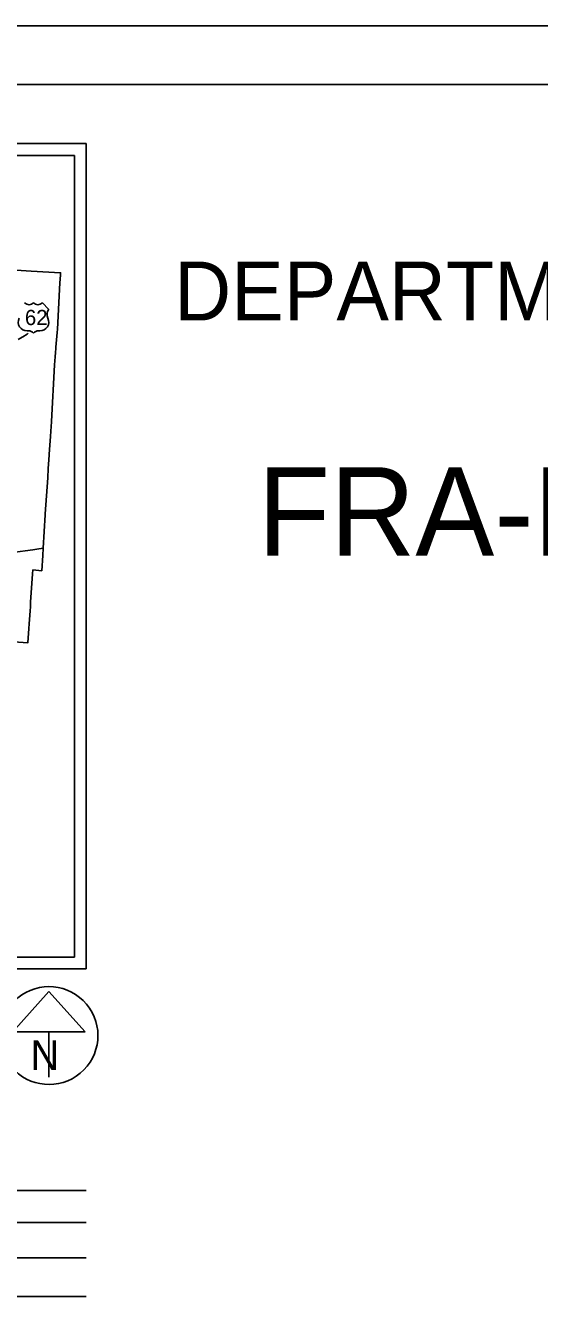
# Model space of a CAD drawing. Extents: x 0 to 34, y 0 to 22.
# Drawn here: x 8.49 to 12.84, y 11.1 to 22 of the extents above; entities that cross this region are included whole.
import ezdxf

# ---------------------------------------------------------------- set-up
doc = ezdxf.new("R2010")
doc.units = 0
for name, color, linetype in [('GM_X_County', 7, 'Continuous'), ('GM_X_State_Route', 7, 'Continuous'), ('GM_X_US_Route', 7, 'Continuous'), ('GM_X_US_Shield', 7, 'Continuous'), ('SH_Border', 7, 'Continuous'), ('SH_Cut_Line', 7, 'Continuous'), ('SH_Data', 7, 'Continuous'), ('SH_Text', 7, 'Continuous')]:
    doc.layers.add(name, color=color, linetype=linetype)

msp = doc.modelspace()

# ---------------------------------------------------------------- linework, layer by layer
at = {"layer": 'GM_X_County'}
msp.add_lwpolyline([(8.407, 19.926), (8.534, 19.918), (8.783, 19.905), (8.782, 19.883), (8.778, 19.818), (8.757, 19.427), (8.756, 19.425), (8.755, 19.398), (8.744, 19.273), (8.744, 19.263), (8.741, 19.229), (8.738, 19.191), (8.733, 19.123), (8.705, 18.642), (8.705, 18.641), (8.7, 18.562), (8.697, 18.517), (8.69, 18.405), (8.684, 18.317), (8.679, 18.246), (8.674, 18.165), (8.669, 18.09), (8.653, 17.859), (8.652, 17.851), (8.636, 17.568), (8.632, 17.506), (8.623, 17.377), (8.548, 17.384), (8.546, 17.35), (8.529, 17.11), (8.527, 17.07), (8.524, 17.037), (8.517, 16.927), (8.514, 16.889), (8.505, 16.766), (8.388, 16.774)], dxfattribs=at)
at = {"layer": 'GM_X_State_Route'}
msp.add_lwpolyline([(8.395, 17.534), (8.397, 17.534), (8.483, 17.546), (8.549, 17.556), (8.582, 17.56), (8.636, 17.568)], dxfattribs=at)
at = {"layer": 'GM_X_US_Route'}
msp.add_lwpolyline([(8.425, 19.339), (8.438, 19.347), (8.462, 19.362), (8.499, 19.385), (8.509, 19.392)], dxfattribs=at)
at = {"layer": 'GM_X_US_Shield'}
for p, q in [((8.682, 19.595), (8.629, 19.649)), ((8.5, 19.412), (8.511, 19.412)), ((8.597, 19.412), (8.607, 19.412))]:
    msp.add_line(p, q, dxfattribs=at)
for centre, radius, start, end in [((8.516, 19.687), 0.0537, 225.573, 314.427), ((8.591, 19.687), 0.0537, 225.573, 314.427), ((8.499, 19.487), 0.0752, 154.8319, 270.6383), ((8.608, 19.487), 0.0752, 269.3617, 25.1681), ((8.744, 19.552), 0.0752, 144.9991, 205.4529), ((8.511, 19.359), 0.0537, 36.8699, 90), ((8.597, 19.359), 0.0537, 90, 143.1301)]:
    msp.add_arc(centre, radius, start, end, dxfattribs=at)
at = {"layer": 'SH_Border'}
msp.add_lwpolyline([(1.5, 21.5), (33.5, 21.5), (33.5, 0.5), (1.5, 0.5)], close=True, dxfattribs=at)
at = {"layer": 'SH_Cut_Line'}
msp.add_lwpolyline([(0, 0), (34, 0), (34, 22), (0, 22)], close=True, dxfattribs=at)
at = {"layer": 'SH_Data'}
for p, q in [((2, 21), (9, 21)), ((9, 21), (9, 14)), ((2.1, 20.9), (8.9, 20.9)), ((8.9, 20.9), (8.9, 14.1)), ((2.1, 14.1), (8.9, 14.1)), ((2, 14), (9, 14)), ((8.685, 13.809), (8.377, 13.468)), ((8.992, 13.468), (8.685, 13.809)), ((8.377, 13.468), (8.992, 13.468)), ((8.685, 13.468), (8.685, 13.081)), ((8.685, 13.435), (8.685, 13.435)), ((8.685, 13.435), (8.685, 13.435)), ((9, 12.121), (7.75, 12.121)), ((9, 11.849), (7.75, 11.849)), ((9, 11.549), (7.75, 11.549)), ((9, 11.222), (7.75, 11.222))]:
    msp.add_line(p, q, dxfattribs=at)
msp.add_arc((8.685, 13.435), 0.415, 129.7798, 129.7633, dxfattribs=at)

# ---------------------------------------------------------------- texts
at = {"layer": 'GM_X_US_Shield'}
msp.add_text('62', height=0.1288, dxfattribs=at).set_placement((8.481, 19.461))
at = {"layer": 'SH_Data'}
msp.add_text('N', height=0.25, dxfattribs=at).set_placement((8.529, 13.144))
at = {"layer": 'SH_Text'}
for s, height, p in [('DEPARTMENT OF TRANSPORTATION', 0.5, (9.747, 19.5)), ('FRA-LITTER/MOW-FY2027', 0.75, (10.455, 17.505))]:
    msp.add_text(s, height=height, dxfattribs=at).set_placement(p)

doc.saveas('drawing.dxf')
